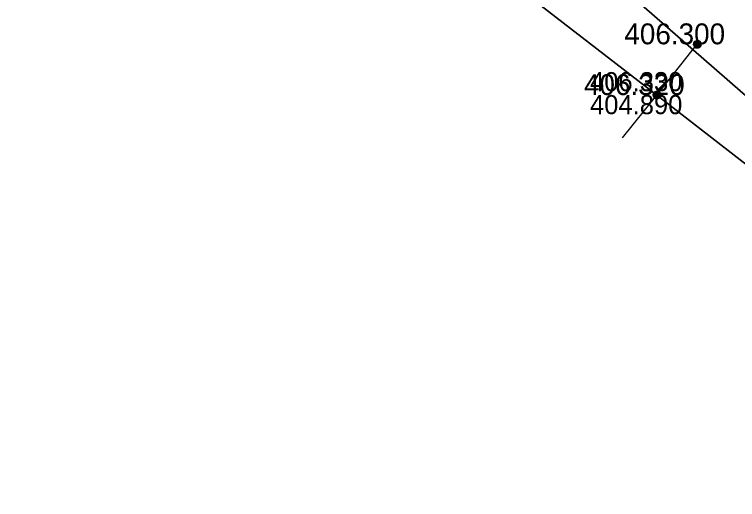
# Model space of a CAD drawing. Extents: x -873619 to -867639, y -1015082 to -1012326.
# Drawn here: x -868171.18 to -868129.55, y -1012775.89 to -1012747.99 of the extents above; entities that cross this region are included whole.
import ezdxf

# ---------------------------------------------------------------- set-up
doc = ezdxf.new("R2010")
doc.units = 0
doc.header["$LTSCALE"] = 0.44
for name, color, linetype, lineweight in [('1', 7, 'Continuous', 13), ('21', 7, 'Continuous', 35), ('23', 7, 'Continuous', 25), ('32', 7, 'Continuous', 13)]:
    doc.layers.add(name, color=color, linetype=linetype, lineweight=lineweight)

msp = doc.modelspace()

# ---------------------------------------------------------------- linework, layer by layer
at = {"layer": '1', "lineweight": 35}
msp.add_lwpolyline([(-868094.808, -1012782.506), (-868128.65, -1012753.034), (-868142.107, -1012741.315), (-868163.447, -1012723.713), (-868165.629, -1012721.604), (-868186.647, -1012703.368), (-868189.69, -1012700.802), (-868224.291, -1012669.746), (-868245.779, -1012651.034), (-868246.236, -1012651.387)], dxfattribs=at)
at = {"layer": '1'}
for points in [[(-868131.634, -1012749.71), (-868131.64, -1012749.658), (-868131.657, -1012749.608), (-868131.686, -1012749.564), (-868131.723, -1012749.527), (-868131.768, -1012749.5), (-868131.818, -1012749.483), (-868131.871, -1012749.479), (-868131.923, -1012749.486), (-868131.972, -1012749.505), (-868132.015, -1012749.534), (-868132.051, -1012749.573), (-868132.077, -1012749.618), (-868132.093, -1012749.669), (-868132.096, -1012749.721), (-868132.088, -1012749.773), (-868132.068, -1012749.822), (-868132.037, -1012749.865), (-868131.998, -1012749.899), (-868131.952, -1012749.925), (-868131.901, -1012749.939), (-868131.848, -1012749.941), (-868131.797, -1012749.931), (-868131.749, -1012749.91), (-868131.706, -1012749.879), (-868131.672, -1012749.838), (-868131.648, -1012749.792), (-868131.636, -1012749.741)], [(-868131.664, -1012749.71), (-868131.67, -1012749.661), (-868131.687, -1012749.615), (-868131.715, -1012749.575), (-868131.752, -1012749.543), (-868131.796, -1012749.521), (-868131.844, -1012749.51), (-868131.893, -1012749.51), (-868131.94, -1012749.523), (-868131.983, -1012749.547), (-868132.019, -1012749.58), (-868132.046, -1012749.621), (-868132.062, -1012749.668), (-868132.066, -1012749.717), (-868132.059, -1012749.765), (-868132.04, -1012749.81), (-868132.01, -1012749.85), (-868131.972, -1012749.881), (-868131.928, -1012749.901), (-868131.88, -1012749.911), (-868131.831, -1012749.909), (-868131.784, -1012749.894), (-868131.741, -1012749.869), (-868131.706, -1012749.835), (-868131.681, -1012749.793), (-868131.667, -1012749.746)], [(-868131.694, -1012749.71), (-868131.7, -1012749.665), (-868131.717, -1012749.623), (-868131.745, -1012749.588), (-868131.781, -1012749.561), (-868131.823, -1012749.544), (-868131.868, -1012749.539), (-868131.913, -1012749.545), (-868131.954, -1012749.564), (-868131.989, -1012749.592), (-868132.016, -1012749.629), (-868132.032, -1012749.671), (-868132.036, -1012749.716), (-868132.029, -1012749.761), (-868132.01, -1012749.802), (-868131.981, -1012749.836), (-868131.944, -1012749.862), (-868131.901, -1012749.878), (-868131.856, -1012749.881), (-868131.811, -1012749.873), (-868131.771, -1012749.853), (-868131.737, -1012749.824), (-868131.711, -1012749.786), (-868131.697, -1012749.743)], [(-868131.724, -1012749.71), (-868131.728, -1012749.669), (-868131.747, -1012749.632), (-868131.774, -1012749.601), (-868131.809, -1012749.58), (-868131.849, -1012749.569), (-868131.89, -1012749.571), (-868131.929, -1012749.584), (-868131.963, -1012749.608), (-868131.988, -1012749.64), (-868132.003, -1012749.678), (-868132.005, -1012749.719), (-868131.998, -1012749.759), (-868131.978, -1012749.795), (-868131.949, -1012749.824), (-868131.912, -1012749.843), (-868131.872, -1012749.851), (-868131.831, -1012749.847), (-868131.793, -1012749.832), (-868131.761, -1012749.806), (-868131.738, -1012749.772), (-868131.725, -1012749.733)], [(-868131.754, -1012749.71), (-868131.759, -1012749.674), (-868131.777, -1012749.642), (-868131.803, -1012749.617), (-868131.837, -1012749.602), (-868131.873, -1012749.599), (-868131.907, -1012749.607), (-868131.939, -1012749.627), (-868131.962, -1012749.655), (-868131.975, -1012749.689), (-868131.975, -1012749.726), (-868131.964, -1012749.761), (-868131.943, -1012749.79), (-868131.913, -1012749.811), (-868131.878, -1012749.821), (-868131.841, -1012749.819), (-868131.807, -1012749.805), (-868131.78, -1012749.782), (-868131.761, -1012749.75), (-868131.754, -1012749.715)], [(-868131.784, -1012749.71), (-868131.789, -1012749.679), (-868131.806, -1012749.653), (-868131.831, -1012749.636), (-868131.862, -1012749.629), (-868131.893, -1012749.633), (-868131.92, -1012749.65), (-868131.938, -1012749.674), (-868131.946, -1012749.705), (-868131.942, -1012749.735), (-868131.927, -1012749.763), (-868131.902, -1012749.782), (-868131.873, -1012749.791), (-868131.842, -1012749.788), (-868131.814, -1012749.774), (-868131.794, -1012749.75), (-868131.784, -1012749.721)], [(-868131.814, -1012749.71), (-868131.819, -1012749.686), (-868131.836, -1012749.668), (-868131.858, -1012749.659), (-868131.883, -1012749.662), (-868131.904, -1012749.676), (-868131.915, -1012749.698), (-868131.915, -1012749.723), (-868131.902, -1012749.744), (-868131.883, -1012749.758), (-868131.858, -1012749.761), (-868131.835, -1012749.752), (-868131.819, -1012749.734)], [(-868131.844, -1012749.71), (-868131.849, -1012749.695), (-868131.864, -1012749.689), (-868131.879, -1012749.693), (-868131.886, -1012749.707), (-868131.882, -1012749.722), (-868131.869, -1012749.731), (-868131.853, -1012749.728), (-868131.844, -1012749.716)], [(-868133.958, -1012752.63), (-868133.965, -1012752.578), (-868133.982, -1012752.528), (-868134.011, -1012752.484), (-868134.048, -1012752.447), (-868134.093, -1012752.42), (-868134.142, -1012752.403), (-868134.196, -1012752.399), (-868134.247, -1012752.406), (-868134.296, -1012752.425), (-868134.34, -1012752.454), (-868134.375, -1012752.493), (-868134.402, -1012752.538), (-868134.418, -1012752.589), (-868134.421, -1012752.641), (-868134.413, -1012752.693), (-868134.392, -1012752.742), (-868134.362, -1012752.785), (-868134.323, -1012752.819), (-868134.277, -1012752.845), (-868134.225, -1012752.859), (-868134.173, -1012752.861), (-868134.122, -1012752.851), (-868134.073, -1012752.83), (-868134.031, -1012752.799), (-868133.997, -1012752.758), (-868133.973, -1012752.712), (-868133.96, -1012752.661)], [(-868133.989, -1012752.63), (-868133.995, -1012752.581), (-868134.012, -1012752.535), (-868134.039, -1012752.495), (-868134.076, -1012752.463), (-868134.12, -1012752.441), (-868134.169, -1012752.43), (-868134.218, -1012752.43), (-868134.264, -1012752.443), (-868134.308, -1012752.467), (-868134.343, -1012752.5), (-868134.37, -1012752.541), (-868134.387, -1012752.588), (-868134.391, -1012752.637), (-868134.384, -1012752.685), (-868134.365, -1012752.73), (-868134.335, -1012752.77), (-868134.296, -1012752.801), (-868134.252, -1012752.821), (-868134.205, -1012752.831), (-868134.156, -1012752.829), (-868134.108, -1012752.814), (-868134.066, -1012752.789), (-868134.031, -1012752.755), (-868134.005, -1012752.713), (-868133.992, -1012752.666)], [(-868134.019, -1012752.63), (-868134.024, -1012752.585), (-868134.041, -1012752.543), (-868134.07, -1012752.508), (-868134.105, -1012752.481), (-868134.147, -1012752.464), (-868134.193, -1012752.459), (-868134.237, -1012752.465), (-868134.279, -1012752.484), (-868134.313, -1012752.512), (-868134.34, -1012752.549), (-868134.357, -1012752.591), (-868134.36, -1012752.636), (-868134.353, -1012752.681), (-868134.335, -1012752.722), (-868134.306, -1012752.756), (-868134.269, -1012752.782), (-868134.225, -1012752.798), (-868134.181, -1012752.801), (-868134.136, -1012752.793), (-868134.095, -1012752.773), (-868134.061, -1012752.744), (-868134.036, -1012752.706), (-868134.022, -1012752.663)], [(-868134.049, -1012752.63), (-868134.053, -1012752.589), (-868134.071, -1012752.552), (-868134.098, -1012752.521), (-868134.134, -1012752.5), (-868134.174, -1012752.489), (-868134.215, -1012752.491), (-868134.254, -1012752.504), (-868134.288, -1012752.528), (-868134.313, -1012752.56), (-868134.328, -1012752.598), (-868134.33, -1012752.639), (-868134.323, -1012752.679), (-868134.303, -1012752.715), (-868134.274, -1012752.744), (-868134.237, -1012752.763), (-868134.196, -1012752.771), (-868134.156, -1012752.767), (-868134.117, -1012752.752), (-868134.085, -1012752.726), (-868134.063, -1012752.692), (-868134.049, -1012752.653)], [(-868134.078, -1012752.63), (-868134.083, -1012752.594), (-868134.102, -1012752.562), (-868134.127, -1012752.537), (-868134.161, -1012752.522), (-868134.198, -1012752.519), (-868134.232, -1012752.527), (-868134.264, -1012752.547), (-868134.286, -1012752.575), (-868134.299, -1012752.609), (-868134.299, -1012752.646), (-868134.289, -1012752.681), (-868134.267, -1012752.71), (-868134.237, -1012752.731), (-868134.203, -1012752.741), (-868134.166, -1012752.739), (-868134.132, -1012752.725), (-868134.105, -1012752.702), (-868134.085, -1012752.67), (-868134.078, -1012752.635)], [(-868134.108, -1012752.63), (-868134.114, -1012752.599), (-868134.13, -1012752.573), (-868134.156, -1012752.556), (-868134.186, -1012752.549), (-868134.218, -1012752.553), (-868134.245, -1012752.57), (-868134.262, -1012752.594), (-868134.271, -1012752.625), (-868134.267, -1012752.655), (-868134.252, -1012752.683), (-868134.227, -1012752.702), (-868134.198, -1012752.711), (-868134.166, -1012752.708), (-868134.139, -1012752.694), (-868134.119, -1012752.67), (-868134.108, -1012752.641)], [(-868134.139, -1012752.63), (-868134.144, -1012752.606), (-868134.161, -1012752.588), (-868134.183, -1012752.579), (-868134.208, -1012752.582), (-868134.228, -1012752.596), (-868134.24, -1012752.618), (-868134.24, -1012752.643), (-868134.227, -1012752.664), (-868134.208, -1012752.678), (-868134.183, -1012752.681), (-868134.159, -1012752.672), (-868134.144, -1012752.654)], [(-868134.169, -1012752.63), (-868134.174, -1012752.615), (-868134.188, -1012752.609), (-868134.203, -1012752.613), (-868134.21, -1012752.627), (-868134.206, -1012752.642), (-868134.193, -1012752.651), (-868134.178, -1012752.648), (-868134.169, -1012752.636)]]:
    msp.add_lwpolyline(points, close=True, dxfattribs=at)
at = {"layer": '21'}
msp.add_line((-868166.248, -1012727.87), (-868134.19, -1012752.63), dxfattribs=at)
msp.add_lwpolyline([(-868134.19, -1012752.63), (-868112.27, -1012769.62), (-868107.42, -1012773.25), (-868101.75, -1012777.58), (-868093.15, -1012793.25), (-868087.37, -1012839.18), (-868062.459, -1012846.83), (-868020.28, -1012856.9)], dxfattribs=at)
at = {"layer": '23'}
for p, q in [((-868134.19, -1012752.63), (-868131.865, -1012749.71)), ((-868136.17, -1012755.09), (-868134.19, -1012752.63))]:
    msp.add_line(p, q, dxfattribs=at)
at = {"layer": '32'}
for points in [[(-868131.634, -1012749.71), (-868131.64, -1012749.658), (-868131.657, -1012749.608), (-868131.686, -1012749.564), (-868131.723, -1012749.527), (-868131.768, -1012749.5), (-868131.818, -1012749.483), (-868131.871, -1012749.479), (-868131.923, -1012749.486), (-868131.972, -1012749.505), (-868132.015, -1012749.534), (-868132.051, -1012749.573), (-868132.077, -1012749.618), (-868132.093, -1012749.669), (-868132.096, -1012749.721), (-868132.088, -1012749.773), (-868132.068, -1012749.822), (-868132.037, -1012749.865), (-868131.998, -1012749.899), (-868131.952, -1012749.925), (-868131.901, -1012749.939), (-868131.848, -1012749.941), (-868131.797, -1012749.931), (-868131.749, -1012749.91), (-868131.706, -1012749.879), (-868131.672, -1012749.838), (-868131.648, -1012749.792), (-868131.636, -1012749.741)], [(-868131.664, -1012749.71), (-868131.67, -1012749.661), (-868131.687, -1012749.615), (-868131.715, -1012749.575), (-868131.752, -1012749.543), (-868131.796, -1012749.521), (-868131.844, -1012749.51), (-868131.893, -1012749.51), (-868131.94, -1012749.523), (-868131.983, -1012749.547), (-868132.019, -1012749.58), (-868132.046, -1012749.621), (-868132.062, -1012749.668), (-868132.066, -1012749.717), (-868132.059, -1012749.765), (-868132.04, -1012749.81), (-868132.01, -1012749.85), (-868131.972, -1012749.881), (-868131.928, -1012749.901), (-868131.88, -1012749.911), (-868131.831, -1012749.909), (-868131.784, -1012749.894), (-868131.741, -1012749.869), (-868131.706, -1012749.835), (-868131.681, -1012749.793), (-868131.667, -1012749.746)], [(-868131.694, -1012749.71), (-868131.7, -1012749.665), (-868131.717, -1012749.623), (-868131.745, -1012749.588), (-868131.781, -1012749.561), (-868131.823, -1012749.544), (-868131.868, -1012749.539), (-868131.913, -1012749.545), (-868131.954, -1012749.564), (-868131.989, -1012749.592), (-868132.016, -1012749.629), (-868132.032, -1012749.671), (-868132.036, -1012749.716), (-868132.029, -1012749.761), (-868132.01, -1012749.802), (-868131.981, -1012749.836), (-868131.944, -1012749.862), (-868131.901, -1012749.878), (-868131.856, -1012749.881), (-868131.811, -1012749.873), (-868131.771, -1012749.853), (-868131.737, -1012749.824), (-868131.711, -1012749.786), (-868131.697, -1012749.743)], [(-868131.724, -1012749.71), (-868131.728, -1012749.669), (-868131.747, -1012749.632), (-868131.774, -1012749.601), (-868131.809, -1012749.58), (-868131.849, -1012749.569), (-868131.89, -1012749.571), (-868131.929, -1012749.584), (-868131.963, -1012749.608), (-868131.988, -1012749.64), (-868132.003, -1012749.678), (-868132.005, -1012749.719), (-868131.998, -1012749.759), (-868131.978, -1012749.795), (-868131.949, -1012749.824), (-868131.912, -1012749.843), (-868131.872, -1012749.851), (-868131.831, -1012749.847), (-868131.793, -1012749.832), (-868131.761, -1012749.806), (-868131.738, -1012749.772), (-868131.725, -1012749.733)], [(-868131.754, -1012749.71), (-868131.759, -1012749.674), (-868131.777, -1012749.642), (-868131.803, -1012749.617), (-868131.837, -1012749.602), (-868131.873, -1012749.599), (-868131.907, -1012749.607), (-868131.939, -1012749.627), (-868131.962, -1012749.655), (-868131.975, -1012749.689), (-868131.975, -1012749.726), (-868131.964, -1012749.761), (-868131.943, -1012749.79), (-868131.913, -1012749.811), (-868131.878, -1012749.821), (-868131.841, -1012749.819), (-868131.807, -1012749.805), (-868131.78, -1012749.782), (-868131.761, -1012749.75), (-868131.754, -1012749.715)], [(-868131.784, -1012749.71), (-868131.789, -1012749.679), (-868131.806, -1012749.653), (-868131.831, -1012749.636), (-868131.862, -1012749.629), (-868131.893, -1012749.633), (-868131.92, -1012749.65), (-868131.938, -1012749.674), (-868131.946, -1012749.705), (-868131.942, -1012749.735), (-868131.927, -1012749.763), (-868131.902, -1012749.782), (-868131.873, -1012749.791), (-868131.842, -1012749.788), (-868131.814, -1012749.774), (-868131.794, -1012749.75), (-868131.784, -1012749.721)], [(-868131.814, -1012749.71), (-868131.819, -1012749.686), (-868131.836, -1012749.668), (-868131.858, -1012749.659), (-868131.883, -1012749.662), (-868131.904, -1012749.676), (-868131.915, -1012749.698), (-868131.915, -1012749.723), (-868131.902, -1012749.744), (-868131.883, -1012749.758), (-868131.858, -1012749.761), (-868131.835, -1012749.752), (-868131.819, -1012749.734)], [(-868131.844, -1012749.71), (-868131.849, -1012749.695), (-868131.864, -1012749.689), (-868131.879, -1012749.693), (-868131.886, -1012749.707), (-868131.882, -1012749.722), (-868131.869, -1012749.731), (-868131.853, -1012749.728), (-868131.844, -1012749.716)], [(-868133.96, -1012752.629), (-868133.966, -1012752.577), (-868133.983, -1012752.527), (-868134.012, -1012752.483), (-868134.049, -1012752.446), (-868134.094, -1012752.419), (-868134.144, -1012752.402), (-868134.197, -1012752.398), (-868134.249, -1012752.405), (-868134.298, -1012752.424), (-868134.341, -1012752.453), (-868134.377, -1012752.492), (-868134.403, -1012752.537), (-868134.419, -1012752.588), (-868134.422, -1012752.64), (-868134.414, -1012752.692), (-868134.394, -1012752.741), (-868134.363, -1012752.784), (-868134.324, -1012752.818), (-868134.278, -1012752.844), (-868134.227, -1012752.858), (-868134.174, -1012752.86), (-868134.123, -1012752.85), (-868134.075, -1012752.829), (-868134.032, -1012752.798), (-868133.998, -1012752.757), (-868133.974, -1012752.711), (-868133.962, -1012752.66)], [(-868133.99, -1012752.629), (-868133.996, -1012752.58), (-868134.013, -1012752.534), (-868134.041, -1012752.494), (-868134.078, -1012752.462), (-868134.122, -1012752.44), (-868134.17, -1012752.429), (-868134.219, -1012752.429), (-868134.266, -1012752.442), (-868134.309, -1012752.466), (-868134.345, -1012752.499), (-868134.372, -1012752.54), (-868134.388, -1012752.587), (-868134.392, -1012752.636), (-868134.385, -1012752.684), (-868134.366, -1012752.729), (-868134.336, -1012752.769), (-868134.298, -1012752.8), (-868134.254, -1012752.82), (-868134.206, -1012752.83), (-868134.157, -1012752.828), (-868134.11, -1012752.813), (-868134.067, -1012752.788), (-868134.032, -1012752.754), (-868134.007, -1012752.712), (-868133.993, -1012752.665)], [(-868134.02, -1012752.629), (-868134.026, -1012752.584), (-868134.043, -1012752.542), (-868134.071, -1012752.507), (-868134.107, -1012752.48), (-868134.149, -1012752.463), (-868134.194, -1012752.458), (-868134.239, -1012752.464), (-868134.28, -1012752.483), (-868134.315, -1012752.511), (-868134.342, -1012752.548), (-868134.358, -1012752.59), (-868134.362, -1012752.635), (-868134.355, -1012752.68), (-868134.336, -1012752.721), (-868134.307, -1012752.755), (-868134.27, -1012752.781), (-868134.227, -1012752.797), (-868134.182, -1012752.8), (-868134.137, -1012752.792), (-868134.097, -1012752.772), (-868134.063, -1012752.743), (-868134.037, -1012752.705), (-868134.023, -1012752.662)], [(-868134.05, -1012752.629), (-868134.054, -1012752.588), (-868134.073, -1012752.551), (-868134.1, -1012752.52), (-868134.135, -1012752.499), (-868134.175, -1012752.488), (-868134.216, -1012752.49), (-868134.255, -1012752.503), (-868134.289, -1012752.527), (-868134.314, -1012752.559), (-868134.329, -1012752.597), (-868134.331, -1012752.638), (-868134.324, -1012752.678), (-868134.304, -1012752.714), (-868134.275, -1012752.743), (-868134.238, -1012752.762), (-868134.198, -1012752.77), (-868134.157, -1012752.766), (-868134.119, -1012752.751), (-868134.087, -1012752.725), (-868134.064, -1012752.691), (-868134.051, -1012752.652)], [(-868134.08, -1012752.629), (-868134.085, -1012752.593), (-868134.103, -1012752.561), (-868134.129, -1012752.536), (-868134.163, -1012752.521), (-868134.199, -1012752.518), (-868134.233, -1012752.526), (-868134.265, -1012752.546), (-868134.288, -1012752.574), (-868134.301, -1012752.608), (-868134.301, -1012752.645), (-868134.29, -1012752.68), (-868134.269, -1012752.709), (-868134.239, -1012752.73), (-868134.204, -1012752.74), (-868134.167, -1012752.738), (-868134.133, -1012752.724), (-868134.106, -1012752.701), (-868134.087, -1012752.669), (-868134.08, -1012752.634)], [(-868134.11, -1012752.629), (-868134.115, -1012752.598), (-868134.132, -1012752.572), (-868134.157, -1012752.555), (-868134.188, -1012752.548), (-868134.219, -1012752.552), (-868134.246, -1012752.569), (-868134.264, -1012752.593), (-868134.272, -1012752.624), (-868134.268, -1012752.654), (-868134.253, -1012752.682), (-868134.228, -1012752.701), (-868134.199, -1012752.71), (-868134.168, -1012752.707), (-868134.14, -1012752.693), (-868134.12, -1012752.669), (-868134.11, -1012752.64)], [(-868134.14, -1012752.629), (-868134.145, -1012752.605), (-868134.162, -1012752.587), (-868134.184, -1012752.578), (-868134.209, -1012752.581), (-868134.23, -1012752.595), (-868134.241, -1012752.617), (-868134.241, -1012752.642), (-868134.228, -1012752.663), (-868134.209, -1012752.677), (-868134.184, -1012752.68), (-868134.161, -1012752.671), (-868134.145, -1012752.653)], [(-868134.17, -1012752.629), (-868134.175, -1012752.614), (-868134.19, -1012752.608), (-868134.205, -1012752.612), (-868134.212, -1012752.626), (-868134.208, -1012752.641), (-868134.195, -1012752.65), (-868134.179, -1012752.647), (-868134.17, -1012752.635)]]:
    msp.add_lwpolyline(points, close=True, dxfattribs=at)

# ---------------------------------------------------------------- texts
at = {"layer": '1'}
for s, height, p in [('406.300 ', 1.2, (-868136.065, -1012749.71)), ('406.330 ', 1.1, (-868138.041, -1012752.409)), ('406.320 ', 1.2, (-868138.39, -1012752.63)), ('404.890 ', 1.1, (-868138.041, -1012753.729))]:
    msp.add_text(s, height=height, dxfattribs=at).set_placement(p)

doc.saveas('drawing.dxf')
